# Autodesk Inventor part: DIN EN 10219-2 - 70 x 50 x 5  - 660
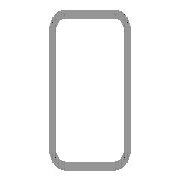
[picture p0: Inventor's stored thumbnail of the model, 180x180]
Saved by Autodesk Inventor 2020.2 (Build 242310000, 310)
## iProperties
IsCustomPart: 1
Created: 2019-01
Part Number: DIN EN 10219-2 - 70 x 50 x 5  - 660
Material: Stahl, weich
Description: Kaltgeformte, geschweißte Baustahl-Hohlprofile aus unlegiertem Feinkorn-Baustahl
Document SubType Name: Modeling
Standard: DIN
Designer: lutzd
Standard Revision: 2006-07
Standards Organization: DIN
Language: de-DE
Size Designation: 70 x 50 x 5
Categories: <MemberInstance><Categories><Category DisplayName="Profile" InternalName="089c4875-fa83-4c05-b084-43b9cc11f5ed" Mnemonic="GRDR"><CategoryParameter DisplayName="
Stock Number: 70 x 50 x 5
Mass: 5351.92 g
Surface Area: 2758.25 cm^2
Volume: 681.774 cm^3
Density: 7.85 g/cm^3
Appearance: Semi-Polished(8)
G_W: 50,000 mm
G_H: 70,000 mm
Mass: 5,352 kg
VLT_Material: Stahl, weich
G_L: 660,000 mm
Dimensions: 50x70x660 mm
+E0B17210-1ED4-4FFA-9E7B-C82048E0192B+SCHNITTDETAIL2: Schnittwinkel 90,00 grd
_CCFamilyMember: 17
_CCFamilyDisplayName: DIN EN 10219-2 (Rechteckiges Hohlprofil - Kaltgeformt) - Kaltgeformte, geschweißte Baustahl-Hohlprofile aus unlegiertem Feinkorn-Baustahl
_FrameMemberDoc: Frame Member File
_Version: 15.0.0
_GetPNFromCC: 1
Author: lutzd
Revision Number: -
Title: Kaltgeformte, geschweißte Baustahl-Hohlprofile aus unlegiertem Feinkorn-Baustahl
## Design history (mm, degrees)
node "Startebene"
node "Endebene"
sketch "Skizze"
  geometry: L1 (-25, -25)-(-25, 25); L2 (-15, 35)-(15, 35); L3 (25, 25)-(25, -25); L4 (15, -35)-(-15, -35); L5 (-15, 30)-(15, 30); L6 (20, 25)-(20, -25); L7 (15, -30)-(-15, -30); L8 (-20, -25)-(-20, 25); L9 (0, 51.899)-(0, -51.899) reference; L10 (-37.899, 0)-(37.899, 0) reference; A1 r 10 centre (-15, -25) between (-25, -25) and (-15, -35); A2 r 10 centre (-15, 25) between (-15, 35) and (-25, 25); A3 r 10 centre (15, 25) between (25, 25) and (15, 35); A4 r 10 centre (15, -25) between (15, -35) and (25, -25); A5 r 5 centre (-15, 25) between (-15, 30) and (-20, 25); A6 r 5 centre (15, 25) between (20, 25) and (15, 30); A7 r 5 centre (15, -25) between (15, -30) and (20, -25); A8 r 5 centre (-15, -25) between (-20, -25) and (-15, -30)
  constraints: 16 end point, 16 point on circle, 8 centre point, 8 tangent, 4 parallel, 3 equal radius, 2 perpendicular, 7 other
  dimensions: "d7" = 10 radius of A1 (= G_IR); "d10" = 70 distance between parallel lines of L2 L4 (= G_H); "d11" = 50 distance between parallel lines of L1 L3 (= G_W); "d12" = 5 distance between parallel lines of L3 L6 (= G_T); "d15" = 35 distance between parallel lines of L2 L10 (= 0.5 x d10); "d16" = 25 distance between parallel lines of L9 L3 (= 0.5 x d11)
extrude "Körper" new body sketch "Skizze" stored distance "d3" = 660 (= G_L); taper "d4" = 0 deg
node "Driven Length"
  sketch "Sketch3"
    geometry: L1 (0, 0)-(10, 0) reference
    constraints: 2 end point, 1 horizontal
  workplane "Work Plane3"
  sketch "Sketch4"
    geometry: L1 (-2, 50)-(12, 50) reference; L2 (-2, 710)-(12, 710) reference
    dimensions: "d18" = 660 distance between parallel lines of L1 L2 (derived)
sketch "Skizze5"
  geometry: L1 (660, 50)-(660, 0) reference; L2 (660, 25)-(544, 25); 3 further points
  constraints: 2 end point, 1 coincident, 1 horizontal, 1 midpoint, 1 point on line
  dimensions: "d19" = 116 distance of L2.start L2.end; "d20" = 90 distance of L2.end point (634, 25)
hole "Bohrung1" sketch "Skizze5" at (544, 25), (634, 25) diameter "d21" = 6.647; stored, may be unused: countersink angle "d25" = 90 deg, drill point angle "d27" = 118 deg; dims "d22" = 16, "d23" = 4, "d24" = 2, "d26" = 8
sketch "Skizze6"
  geometry: L1 (440, 41)-(440, 9); L2 (660, 50)-(660, 0) reference; L3 (98, 41)-(98, 9); 8 further points
  constraints: 4 coincident, 4 end point, 3 midpoint, 2 horizontal alignment, 2 vertical
  dimensions: "d28" = 32 distance of L1.start L1.end; "d29" = 220 distance between parallel lines of L2 L1; "d30" = 342 distance between parallel lines of L1 L3; "d31" = 32 distance of L3.start L3.end (= d28)
hole "Bohrung2" sketch "Skizze6" at (440, 9), (440, 41), (98, 9), (98, 41) diameter "d32" = 6.647; stored, may be unused: countersink angle "d36" = 90 deg, drill point angle "d38" = 118 deg; dims "d33" = 16, "d34" = 4, "d35" = 2, "d37" = 8
sketch "Skizze7"
  geometry: L1 (-30, 660)-(0, 660) reference; L2 (-15, 660)-(-15, 224); 5 further points
  constraints: 3 point on line, 2 end point, 1 coincident, 1 midpoint, 1 vertical
  dimensions: "d39" = 436 distance of L2.start L2.end; "d40" = 32 distance of L2.end point (-15, 256); "d41" = 32 distance of point (-15, 454) point (-15, 486) (= d40); "d42" = 206 distance from line of L1 point (-15, 454)
hole "Bohrung3" sketch "Skizze7" at (-15, 256), (-15, 224), (-15, 486), (-15, 454) diameter "d43" = 6.647; stored, may be unused: countersink angle "d47" = 90 deg, drill point angle "d49" = 118 deg; dims "d44" = 16, "d45" = 4, "d46" = 2, "d48" = 8
workplane "Arbeitsebene6"
feature "Trennen3"
body "Solid1"
other parameters: "G_W" = 50 [user parameter; used in 1 equation term], "G_H" = 70 [user parameter; used in 1 equation term], "G_T" = 5 [user parameter; used in 1 equation term], "G_IR" = 10 [user parameter; used in 1 equation term], "G_L" = 660 (= d18) [user parameter; used in 1 equation term], "G_OFFSET_END" = 0 [user parameter; used in 1 equation term], "d17" = 90 deg
